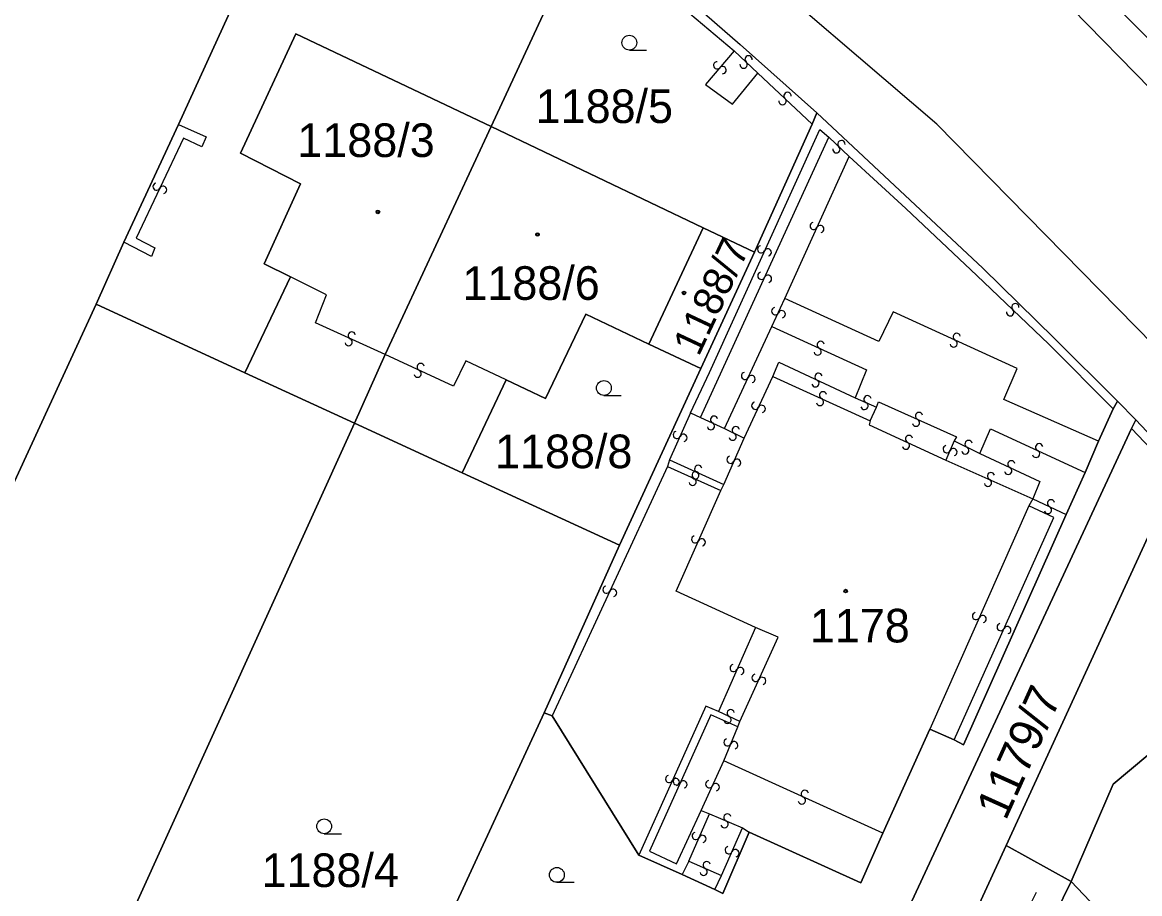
# Model space of a CAD drawing. Extents: x -600309 to -598967, y -1161267 to -1160292.
# Drawn here: x -600001.8 to -599945.2, y -1160464.3 to -1160420.2 of the extents above; entities that cross this region are included whole.
import ezdxf

# ---------------------------------------------------------------- set-up
doc = ezdxf.new("R2010")
doc.units = 0
for name, color, linetype in [('Level 1', 7, 'Continuous'), ('Level 13', 7, 'Continuous'), ('Level 3', 7, 'Continuous'), ('Level 4', 7, 'Continuous'), ('Level 5', 7, 'Continuous'), ('Level 60', 7, 'Continuous'), ('Vrstva 60', 7, 'Continuous')]:
    doc.layers.add(name, color=color, linetype=linetype)

msp = doc.modelspace()

# ---------------------------------------------------------------- linework, layer by layer
at = {"layer": 'Level 1'}
for points in [[(-599993.87, -1160425.35), (-599985.25, -1160406.48)], [(-599973.13, -1160414.83), (-599968.95, -1160418.24), (-599965.44, -1160421.3), (-599961.56, -1160424.77)], [(-599973.35, -1160415.33), (-599978.05, -1160425.46)], [(-599978.05, -1160425.46), (-599987.94, -1160420.76), (-599990.74, -1160426.81), (-599987.69, -1160428.35), (-599989.54, -1160432.4), (-599988.2, -1160433.06)], [(-599961.8, -1160425.34), (-599961.56, -1160424.77)], [(-599961.56, -1160424.77), (-599953.16, -1160432.63), (-599949.52, -1160436.18), (-599946.34, -1160439.35)], [(-599996.65, -1160431.31), (-599993.87, -1160425.35)], [(-599978.05, -1160425.46), (-599983.42, -1160437)], [(-599967.32, -1160430.58), (-599978.05, -1160425.46)], [(-599964.72, -1160431.81), (-599961.8, -1160425.34)], [(-599967.32, -1160430.58), (-599970.06, -1160436.48)], [(-599964.72, -1160431.81), (-599967.32, -1160430.58)], [(-599998.05, -1160434.45), (-599996.65, -1160431.31)], [(-599967.43, -1160437.7), (-599964.72, -1160431.81)], [(-599988.2, -1160433.06), (-599990.52, -1160437.93)], [(-600007.2, -1160454.31), (-599998.05, -1160434.45)], [(-599998.05, -1160434.45), (-599990.52, -1160437.93)], [(-599970.06, -1160436.48), (-599973.26, -1160434.95), (-599975.3, -1160439.22), (-599977.28, -1160438.28)], [(-599967.43, -1160437.7), (-599970.06, -1160436.48)], [(-599983.42, -1160437), (-599984.97, -1160440.48)], [(-599990.52, -1160437.93), (-599984.97, -1160440.48)], [(-599971.55, -1160446.64), (-599967.43, -1160437.7)], [(-599977.28, -1160438.28), (-599979.51, -1160442.99)], [(-599946.34, -1160439.35), (-599946.56, -1160439.75)], [(-599946.34, -1160439.35), (-599945.4, -1160440.31)], [(-599946.56, -1160439.75), (-599947.29, -1160441.39)], [(-599984.97, -1160440.48), (-600000.96, -1160475.68)], [(-599984.97, -1160440.48), (-599979.51, -1160442.99)], [(-599945.4, -1160440.31), (-599945.63, -1160440.74)], [(-599945.4, -1160440.31), (-599943.16, -1160442.68)], [(-599945.63, -1160440.74), (-599958.85, -1160469.21)], [(-599947.29, -1160441.39), (-599947.98, -1160442.97)], [(-599979.51, -1160442.99), (-599971.55, -1160446.64)], [(-599951.98, -1160461.84), (-599943.36, -1160443.12)], [(-599947.98, -1160442.97), (-599948.93, -1160445.09)], [(-599948.93, -1160445.09), (-599954.14, -1160456.75), (-599954.61, -1160456.5)], [(-599975.37, -1160455.13), (-599971.55, -1160446.64)], [(-599948.69, -1160463.67), (-599946.56, -1160458.74), (-599940.46, -1160453.65), (-599938.33, -1160456.19)], [(-599980.19, -1160465.58), (-599975.37, -1160455.13)], [(-599974.95, -1160455.29), (-599975.37, -1160455.13)], [(-599970.57, -1160462.33), (-599974.95, -1160455.29)], [(-599955.84, -1160455.96), (-599958.21, -1160461.23)], [(-599954.61, -1160456.5), (-599955.84, -1160455.96)], [(-599964.98, -1160461.18), (-599966.31, -1160464.27), (-599966.73, -1160464.08)], [(-599958.21, -1160461.23), (-599959.33, -1160463.73), (-599964.98, -1160461.18)], [(-599955.99, -1160470.57), (-599951.98, -1160461.84)], [(-599948.69, -1160463.67), (-599951.98, -1160461.84)], [(-599968.38, -1160463.31), (-599970.57, -1160462.33)], [(-599966.73, -1160464.08), (-599968.38, -1160463.31)], [(-599948.69, -1160463.67), (-599955.2, -1160476.96), (-599958.32, -1160475.66)], [(-599934.41, -1160465.64), (-599937.41, -1160468.09), (-599937.64, -1160467.78), (-599941.92, -1160471.38), (-599943.74, -1160469.17), (-599944.23, -1160469.58), (-599945.99, -1160470.02), (-599947.67, -1160468.07), (-599946.84, -1160466.25), (-599946.45, -1160466.01), (-599948.69, -1160463.67)]]:
    msp.add_lwpolyline(points, dxfattribs=at)
at = {"layer": 'Level 13'}
for centre, start, end in [((-599966.61, -1160422.36), 86.6961, 319.2861), ((-599965.266, -1160422.324), 174.1332, 46.7232), ((-599965.013, -1160422.056), 354.3477, 226.4457), ((-599966.331, -1160422.601), 266.9105, 139.0085), ((-599963.297, -1160424.173), 173.7703, 46.3603), ((-599963.042, -1160423.907), 353.9848, 226.0828), ((-599960.312, -1160426.347), 354.0911, 226.1891), ((-599960.567, -1160426.613), 173.8766, 46.4666), ((-599994.986, -1160428.501), 101.8267, 334.4167), ((-599994.654, -1160428.66), 282.0411, 154.1391), ((-599961.717, -1160430.492), 103.0128, 335.1108), ((-599961.383, -1160430.647), 282.7983, 155.3883), ((-599964.377, -1160431.672), 102.9498, 335.0478), ((-599964.043, -1160431.827), 282.7354, 155.3254), ((-599964.367, -1160433.012), 102.7464, 334.8444), ((-599964.033, -1160433.167), 282.5319, 155.1219), ((-599963.667, -1160434.801), 102.6234, 334.7214), ((-599963.333, -1160434.958), 282.4089, 154.9989), ((-599951.768, -1160434.862), 173.2847, 45.8747), ((-599951.511, -1160434.598), 353.4992, 225.5972), ((-599985.103, -1160436.033), 12.5796, 245.1696), ((-599954.473, -1160436.103), 12.5221, 245.1121), ((-599985.258, -1160436.367), 192.794, 64.892), ((-599961.361, -1160436.513), 12.6584, 244.7564), ((-599954.628, -1160436.437), 192.7366, 64.8346), ((-599961.518, -1160436.847), 192.444, 65.034), ((-599981.612, -1160437.633), 12.4041, 244.9941), ((-599981.769, -1160437.967), 192.6185, 64.7165), ((-599965.196, -1160438.081), 102.3801, 334.4781), ((-599964.864, -1160438.238), 282.1657, 154.7557), ((-599961.471, -1160438.123), 12.4288, 244.5268), ((-599961.628, -1160438.457), 192.2144, 64.8044), ((-599961.397, -1160439.397), 192.6792, 65.2692), ((-599961.242, -1160439.063), 12.8937, 244.9917), ((-599958.994, -1160439.262), 13.6056, 245.7036), ((-599964.676, -1160439.59), 102.2956, 334.3935), ((-599964.344, -1160439.749), 282.0811, 154.6711), ((-599959.145, -1160439.598), 193.3912, 65.9812), ((-599966.919, -1160440.626), 191.9344, 64.5244), ((-599966.76, -1160440.294), 12.1488, 244.2468), ((-599956.536, -1160440.448), 192.9546, 65.5446), ((-599956.383, -1160440.112), 13.1691, 245.2671), ((-599968.648, -1160441.065), 103.3523, 335.9423), ((-599968.312, -1160441.216), 283.5668, 155.6648), ((-599965.82, -1160441.156), 191.5173, 64.1073), ((-599965.659, -1160440.824), 11.7317, 243.8297), ((-599957.048, -1160441.607), 192.4486, 65.0386), ((-599956.891, -1160441.273), 12.663, 244.761), ((-599954.979, -1160441.786), 103.7462, 336.3362), ((-599953.877, -1160441.526), 10.9856, 243.0836), ((-599950.301, -1160441.693), 12.6052, 244.7032), ((-599965.928, -1160442.324), 103.615, 335.713), ((-599954.641, -1160441.935), 283.9606, 156.0586), ((-599954.043, -1160441.855), 190.7712, 63.3612), ((-599950.458, -1160442.027), 192.3907, 64.9807), ((-599967.562, -1160442.783), 13.0234, 245.1214), ((-599965.592, -1160442.475), 283.4006, 155.9906), ((-599951.869, -1160442.886), 192.1208, 64.7108), ((-599951.71, -1160442.554), 12.3352, 244.4332), ((-599967.847, -1160443.437), 192.8424, 65.4324), ((-599967.717, -1160443.117), 192.8089, 65.3989), ((-599967.693, -1160443.103), 13.0568, 245.1548), ((-599952.743, -1160443.152), 13.3134, 245.4114), ((-599952.896, -1160443.488), 193.099, 65.689), ((-599949.701, -1160444.533), 12.4482, 244.5462), ((-599949.858, -1160444.867), 192.2337, 64.8237), ((-599967.718, -1160446.354), 103.4728, 335.5708), ((-599967.382, -1160446.505), 283.2584, 155.8484), ((-599972.207, -1160448.902), 102.3803, 334.9703), ((-599971.873, -1160449.059), 282.5947, 154.6927), ((-599953.498, -1160450.235), 103.2052, 335.7952), ((-599953.162, -1160450.386), 283.4197, 155.5177), ((-599952.248, -1160450.793), 103.217, 335.315), ((-599951.912, -1160450.946), 283.0025, 155.5925), ((-599965.768, -1160452.865), 103.4088, 335.9988), ((-599965.432, -1160453.016), 283.6232, 155.7212), ((-599964.657, -1160453.362), 102.9998, 335.0978), ((-599964.323, -1160453.517), 282.7853, 155.3753), ((-599965.921, -1160455.154), 12.0839, 244.6739), ((-599966.08, -1160455.486), 192.2983, 64.3963), ((-599966.079, -1160456.627), 104.5391, 336.6371), ((-599965.741, -1160456.772), 284.3246, 156.9146), ((-599969.037, -1160458.484), 102.8863, 335.4763), ((-599968.703, -1160458.637), 283.1008, 155.1988), ((-599968.648, -1160458.604), 102.9651, 335.5551), ((-599968.312, -1160458.757), 283.1795, 155.2775), ((-599967.007, -1160458.742), 102.757, 334.855), ((-599966.673, -1160458.897), 282.5426, 155.1326), ((-599962.163, -1160459.233), 12.6768, 245.2668), ((-599962.318, -1160459.567), 192.8913, 64.9893), ((-599966.085, -1160460.431), 14.05, 246.148), ((-599966.234, -1160460.769), 193.8356, 66.4256), ((-599967.688, -1160461.365), 103.7434, 335.8414), ((-599967.352, -1160461.515), 283.5289, 156.1189), ((-599966.018, -1160462.084), 103.6312, 335.7292), ((-599965.682, -1160462.235), 283.4167, 156.0068), ((-599967.285, -1160463.178), 193.4204, 66.0104), ((-599967.134, -1160462.842), 13.6348, 245.7328)]:
    msp.add_arc(centre, 0.184, start, end, dxfattribs=at)
at = {"layer": 'Level 3'}
for points in [[(-599912.7, -1160482.51), (-599912.12, -1160481.96), (-599911.66, -1160481.24), (-599911.44, -1160480.44), (-599911.45, -1160479.4), (-599911.76, -1160478.46), (-599912.23, -1160477.79), (-599914.13, -1160474.8), (-599932.72, -1160449.47), (-599939, -1160442.13), (-599955.49, -1160425.33), (-599966.09, -1160416.24), (-599973.86, -1160410.16), (-599982.22, -1160404.39), (-599992.61, -1160397.63), (-600009.1, -1160386.91), (-600023.99, -1160377.27), (-600035.97, -1160369.05), (-600043.73, -1160362.3), (-600044.47, -1160362.08), (-600045.32, -1160361.98), (-600046.31, -1160362.05), (-600047.41, -1160362.36), (-600048.26, -1160362.83)], [(-599901.41, -1160472.78), (-599910.27, -1160459.71), (-599924.27, -1160442.31), (-599931.25, -1160434.45), (-599947.6, -1160418.18), (-599957.76, -1160408.5)], [(-599957.76, -1160408.5), (-599957.51, -1160409.77), (-599956.19, -1160412.38), (-599954, -1160414.82), (-599948.65, -1160419.48), (-599932.65, -1160435.82), (-599925.74, -1160443.45), (-599912.35, -1160461.36), (-599905.69, -1160471.3), (-599905.11, -1160471.92), (-599904.47, -1160472.37), (-599903.53, -1160472.77), (-599902.42, -1160472.91), (-599901.41, -1160472.78)], [(-599973.35, -1160415.33), (-599969.27, -1160418.64), (-599965.74, -1160421.63)], [(-599965.74, -1160421.63), (-599967.19, -1160423.33), (-599965.82, -1160424.33), (-599964.54, -1160422.75)], [(-599965.74, -1160421.63), (-599964.54, -1160422.75)], [(-599964.54, -1160422.75), (-599961.8, -1160425.34)], [(-599993.87, -1160425.35), (-599992.47, -1160425.98), (-599992.7, -1160426.49), (-599993.62, -1160426.04), (-599996.02, -1160431.11), (-599995.07, -1160431.6), (-599995.24, -1160432.03), (-599996.65, -1160431.31)], [(-599967.96, -1160439.95), (-599967, -1160437.91), (-599961.41, -1160425.6), (-599960.95, -1160426)], [(-599967.45, -1160440.18), (-599960.95, -1160426)], [(-599960.95, -1160426), (-599959.92, -1160426.97)], [(-599963.18, -1160434.17), (-599959.92, -1160426.97)], [(-599959.92, -1160426.97), (-599957.06, -1160429.61), (-599953.45, -1160432.99), (-599949.82, -1160436.48), (-599946.56, -1160439.75)], [(-599983.42, -1160437), (-599986.94, -1160435.39), (-599986.38, -1160433.97), (-599988.2, -1160433.06)], [(-599963.83, -1160435.58), (-599963.18, -1160434.17)], [(-599947.29, -1160441.39), (-599952.09, -1160439.27), (-599951.41, -1160437.71), (-599957.69, -1160434.83), (-599958.42, -1160436.34), (-599963.18, -1160434.17)], [(-599966.24, -1160440.75), (-599963.83, -1160435.58)], [(-599963.83, -1160435.58), (-599959.05, -1160437.78), (-599959.62, -1160439.19)], [(-599977.28, -1160438.28), (-599979.32, -1160437.31), (-599979.95, -1160438.6), (-599983.42, -1160437)], [(-599963.78, -1160438.11), (-599963.49, -1160437.39), (-599959.62, -1160439.19)], [(-599965.24, -1160441.23), (-599963.78, -1160438.11)], [(-599963.78, -1160438.11), (-599958.86, -1160440.35)], [(-599959.62, -1160439.19), (-599958.53, -1160439.67)], [(-599958.86, -1160440.35), (-599958.53, -1160439.67)], [(-599958.53, -1160439.67), (-599958.44, -1160439.39), (-599954.48, -1160441.17), (-599954.6, -1160441.37)], [(-599967.96, -1160439.95), (-599969.01, -1160442.33)], [(-599967.96, -1160439.95), (-599967.45, -1160440.18)], [(-599967.45, -1160440.18), (-599966.24, -1160440.75)], [(-599958.86, -1160440.35), (-599958.91, -1160440.55), (-599955.02, -1160442.34)], [(-599966.24, -1160440.75), (-599965.24, -1160441.23)], [(-599953.31, -1160442.01), (-599952.77, -1160440.76), (-599947.98, -1160442.97)], [(-599945.63, -1160440.74), (-599943.36, -1160443.12)], [(-599966.27, -1160443.57), (-599965.24, -1160441.23)], [(-599954.6, -1160441.37), (-599955.02, -1160442.34)], [(-599954.6, -1160441.37), (-599953.31, -1160442.01)], [(-599953.31, -1160442.01), (-599950.27, -1160443.43), (-599950.63, -1160444.3)], [(-599969.12, -1160442.66), (-599974.95, -1160455.29)], [(-599969.01, -1160442.33), (-599969.12, -1160442.66)], [(-599969.12, -1160442.66), (-599966.42, -1160443.88)], [(-599969.01, -1160442.33), (-599966.27, -1160443.57)], [(-599955.02, -1160442.34), (-599950.63, -1160444.3)], [(-599966.42, -1160443.88), (-599966.27, -1160443.57)], [(-599964.67, -1160450.81), (-599968.68, -1160448.98), (-599966.42, -1160443.88)], [(-599950.63, -1160444.3), (-599950.82, -1160444.66)], [(-599950.63, -1160444.3), (-599948.93, -1160445.09)], [(-599950.82, -1160444.66), (-599955.84, -1160455.96)], [(-599954.61, -1160456.5), (-599949.56, -1160445.24), (-599950.82, -1160444.66)], [(-599964.67, -1160450.81), (-599966.54, -1160455.06)], [(-599965.45, -1160455.57), (-599963.52, -1160451.31), (-599964.67, -1160450.81)], [(-599966.54, -1160455.06), (-599967.17, -1160454.79), (-599970.57, -1160462.33)], [(-599965.45, -1160455.57), (-599966.54, -1160455.06)], [(-599965.55, -1160455.85), (-599966.93, -1160455.23), (-599970.03, -1160462.13), (-599968.66, -1160462.78), (-599967.42, -1160460.07)], [(-599965.55, -1160455.85), (-599965.45, -1160455.57)], [(-599966.27, -1160457.56), (-599965.55, -1160455.85)], [(-599967.42, -1160460.07), (-599966.27, -1160457.56)], [(-599958.21, -1160461.23), (-599966.27, -1160457.56)], [(-599968.04, -1160462.64), (-599966.99, -1160460.24)], [(-599967.42, -1160460.07), (-599966.99, -1160460.24)], [(-599966.99, -1160460.24), (-599965.32, -1160460.96)], [(-599966.38, -1160463.37), (-599965.32, -1160460.96)], [(-599965.32, -1160460.96), (-599964.98, -1160461.18)], [(-599968.04, -1160462.64), (-599968.38, -1160463.31)], [(-599968.04, -1160462.64), (-599966.38, -1160463.37)], [(-599966.73, -1160464.08), (-599966.38, -1160463.37)]]:
    msp.add_lwpolyline(points, dxfattribs=at)
at = {"layer": 'Level 5'}
for p, q in [((-599971.05, -1160421.59), (-599970.175, -1160421.59)), ((-599972.34, -1160439.07), (-599971.465, -1160439.07)), ((-599986.5, -1160461.25), (-599985.625, -1160461.25)), ((-599974.72, -1160463.71), (-599973.845, -1160463.71)), ((-599950.83, -1160464.99), (-599950.445, -1160464.204))]:
    msp.add_line(p, q, dxfattribs=at)
for centre, radius in [((-599971.05, -1160421.215), 0.375), ((-599983.78, -1160429.78), 0.09), ((-599983.78, -1160429.78), 0.0521), ((-599975.7, -1160430.92), 0.09), ((-599975.7, -1160430.92), 0.0521), ((-599968.28, -1160433.88), 0.09), ((-599968.28, -1160433.88), 0.0521), ((-599972.34, -1160438.695), 0.375), ((-599960.1, -1160448.97), 0.09), ((-599960.1, -1160448.97), 0.0521), ((-599986.5, -1160460.875), 0.375), ((-599974.72, -1160463.335), 0.375)]:
    msp.add_circle(centre, radius, dxfattribs=at)
at = {"layer": 'Level 60'}
for points in [[(-599998.05, -1160434.45), (-600007.2, -1160454.31), (-600028.59, -1160444.1), (-600023.36, -1160432.59), (-600005.13, -1160393.36), (-600005, -1160393.09), (-600002.57, -1160394.53), (-600000.04, -1160396.18), (-600002.79, -1160401.73), (-600005.24, -1160407.73), (-600002.19, -1160409.03), (-600004.24, -1160414.02), (-599995.28, -1160417.9), (-599991.25, -1160408.29), (-600000.01, -1160404.57), (-599999.45, -1160403.16), (-599997.23, -1160397.94), (-599985.95, -1160405.27), (-599985.04, -1160405.92), (-599985.25, -1160406.48), (-599993.87, -1160425.35), (-599996.65, -1160431.31)], [(-599990.52, -1160437.93), (-599998.05, -1160434.45), (-599996.65, -1160431.31), (-599993.87, -1160425.35), (-599985.25, -1160406.48), (-599985.04, -1160405.92), (-599980.78, -1160408.96), (-599976.81, -1160411.91), (-599973.13, -1160414.83), (-599973.35, -1160415.33), (-599978.05, -1160425.46), (-599987.94, -1160420.76), (-599990.74, -1160426.81), (-599987.69, -1160428.35), (-599989.54, -1160432.4), (-599988.2, -1160433.06)], [(-599961.8, -1160425.34), (-599964.72, -1160431.81), (-599967.32, -1160430.58), (-599978.05, -1160425.46), (-599973.35, -1160415.33), (-599973.13, -1160414.83), (-599968.95, -1160418.24), (-599965.44, -1160421.3), (-599961.56, -1160424.77)], [(-599984.97, -1160440.48), (-599990.52, -1160437.93), (-599988.2, -1160433.06), (-599989.54, -1160432.4), (-599987.69, -1160428.35), (-599990.74, -1160426.81), (-599987.94, -1160420.76), (-599978.05, -1160425.46), (-599983.42, -1160437)], [(-599946.34, -1160439.35), (-599946.56, -1160439.75), (-599947.29, -1160441.39), (-599947.98, -1160442.97), (-599948.93, -1160445.09), (-599954.14, -1160456.75), (-599954.61, -1160456.5), (-599955.84, -1160455.96), (-599958.21, -1160461.23), (-599959.33, -1160463.73), (-599964.98, -1160461.18), (-599966.31, -1160464.27), (-599966.73, -1160464.08), (-599968.38, -1160463.31), (-599970.57, -1160462.33), (-599974.95, -1160455.29), (-599975.37, -1160455.13), (-599971.55, -1160446.64), (-599967.43, -1160437.7), (-599964.72, -1160431.81), (-599961.8, -1160425.34), (-599961.56, -1160424.77), (-599953.16, -1160432.63), (-599949.52, -1160436.18)], [(-599983.42, -1160437), (-599978.05, -1160425.46), (-599967.32, -1160430.58), (-599970.06, -1160436.48), (-599973.26, -1160434.95), (-599975.3, -1160439.22), (-599977.28, -1160438.28), (-599979.51, -1160442.99), (-599984.97, -1160440.48)], [(-599964.72, -1160431.81), (-599967.43, -1160437.7), (-599970.06, -1160436.48), (-599967.32, -1160430.58)], [(-600000.96, -1160475.68), (-600013.71, -1160468.49), (-600007.2, -1160454.31), (-599998.05, -1160434.45), (-599990.52, -1160437.93), (-599984.97, -1160440.48)], [(-599967.43, -1160437.7), (-599971.55, -1160446.64), (-599979.51, -1160442.99), (-599977.28, -1160438.28), (-599975.3, -1160439.22), (-599973.26, -1160434.95), (-599970.06, -1160436.48)], [(-599971.55, -1160446.64), (-599975.37, -1160455.13), (-599980.19, -1160465.58), (-599980.33, -1160465.9), (-599980.92, -1160467.16), (-599988.18, -1160482.9), (-600000.96, -1160475.68), (-599984.97, -1160440.48), (-599979.51, -1160442.99)], [(-599945.63, -1160440.74), (-599945.4, -1160440.31), (-599943.16, -1160442.68), (-599943.36, -1160443.12), (-599951.98, -1160461.84), (-599955.99, -1160470.57), (-599958.85, -1160469.21)], [(-599934.31, -1160452.98), (-599938.33, -1160456.19), (-599940.46, -1160453.65), (-599946.56, -1160458.74), (-599948.69, -1160463.67), (-599951.98, -1160461.84), (-599943.36, -1160443.12), (-599943.16, -1160442.68), (-599939.54, -1160446.9), (-599935.6, -1160451.43)], [(-599934.41, -1160465.64), (-599937.41, -1160468.09), (-599937.64, -1160467.78), (-599941.92, -1160471.38), (-599943.74, -1160469.17), (-599944.23, -1160469.58), (-599945.99, -1160470.02), (-599947.67, -1160468.07), (-599946.84, -1160466.25), (-599946.45, -1160466.01), (-599948.69, -1160463.67), (-599946.56, -1160458.74), (-599940.46, -1160453.65), (-599938.33, -1160456.19), (-599937.59, -1160457.07), (-599932.12, -1160463.66), (-599933.68, -1160465.04)], [(-599951.98, -1160461.84), (-599948.69, -1160463.67), (-599955.2, -1160476.96), (-599958.32, -1160475.66), (-599955.99, -1160470.57)], [(-599931.32, -1160469.28), (-599950.1, -1160484.05), (-599959.22, -1160477.62), (-599958.56, -1160476.1), (-599958.43, -1160475.89), (-599958.32, -1160475.66), (-599955.2, -1160476.96), (-599948.69, -1160463.67), (-599946.45, -1160466.01), (-599946.84, -1160466.25), (-599947.67, -1160468.07), (-599945.99, -1160470.02), (-599944.23, -1160469.58), (-599943.74, -1160469.17), (-599941.92, -1160471.38), (-599937.64, -1160467.78), (-599937.41, -1160468.09), (-599934.41, -1160465.64)]]:
    msp.add_lwpolyline(points, close=True, dxfattribs=at)
msp.add_lwpolyline([(-599980.19, -1160465.58), (-599975.37, -1160455.13), (-599974.95, -1160455.29), (-599970.57, -1160462.33), (-599968.38, -1160463.31), (-599966.73, -1160464.08), (-599966.31, -1160464.27), (-599964.98, -1160461.18), (-599959.33, -1160463.73), (-599958.21, -1160461.23), (-599955.84, -1160455.96), (-599954.61, -1160456.5), (-599954.14, -1160456.75), (-599948.93, -1160445.09), (-599947.98, -1160442.97), (-599947.29, -1160441.39), (-599946.56, -1160439.75), (-599946.34, -1160439.35), (-599945.4, -1160440.31), (-599945.63, -1160440.74), (-599958.85, -1160469.21)], dxfattribs=at)
at = {"layer": 'Vrstva 60'}
msp.add_lwpolyline([(-599968.95, -1160418.24), (-599965.44, -1160421.3), (-599961.56, -1160424.77), (-599953.16, -1160432.63), (-599949.52, -1160436.18), (-599946.34, -1160439.35), (-599945.4, -1160440.31), (-599943.16, -1160442.68), (-599939.54, -1160446.9), (-599935.6, -1160451.43), (-599934.31, -1160452.98), (-599933.58, -1160453.85), (-599931.35, -1160456.52), (-599928.56, -1160459.93), (-599925.15, -1160464.3), (-599922.17, -1160468.32), (-599919.11, -1160472.75), (-599915.84, -1160477.7), (-599913.69, -1160480.84), (-599912.7, -1160482.51), (-599909.47, -1160487.96)], dxfattribs=at)

# ---------------------------------------------------------------- texts
at = {"layer": 'Level 4'}
for s, p in [('1188/5', (-599975.792, -1160425.28)), ('1188/3', (-599987.857, -1160427)), ('1188/6', (-599979.5, -1160434.23)), ('1188/8', (-599977.848, -1160442.75)), ('1178', (-599961.911, -1160451.57)), ('1188/4', (-599989.67, -1160463.95))]:
    msp.add_text(s, height=1.7, dxfattribs=at).set_placement(p)
for s, height, rotation, p in [('1188/7', 1.5, 64.8, (-599967.54, -1160437.14)), ('1179/7', 1.7, 65.7, (-599951.995, -1160460.631))]:
    msp.add_text(s, height=height, rotation=rotation, dxfattribs=at).set_placement(p)

doc.saveas('drawing.dxf')
